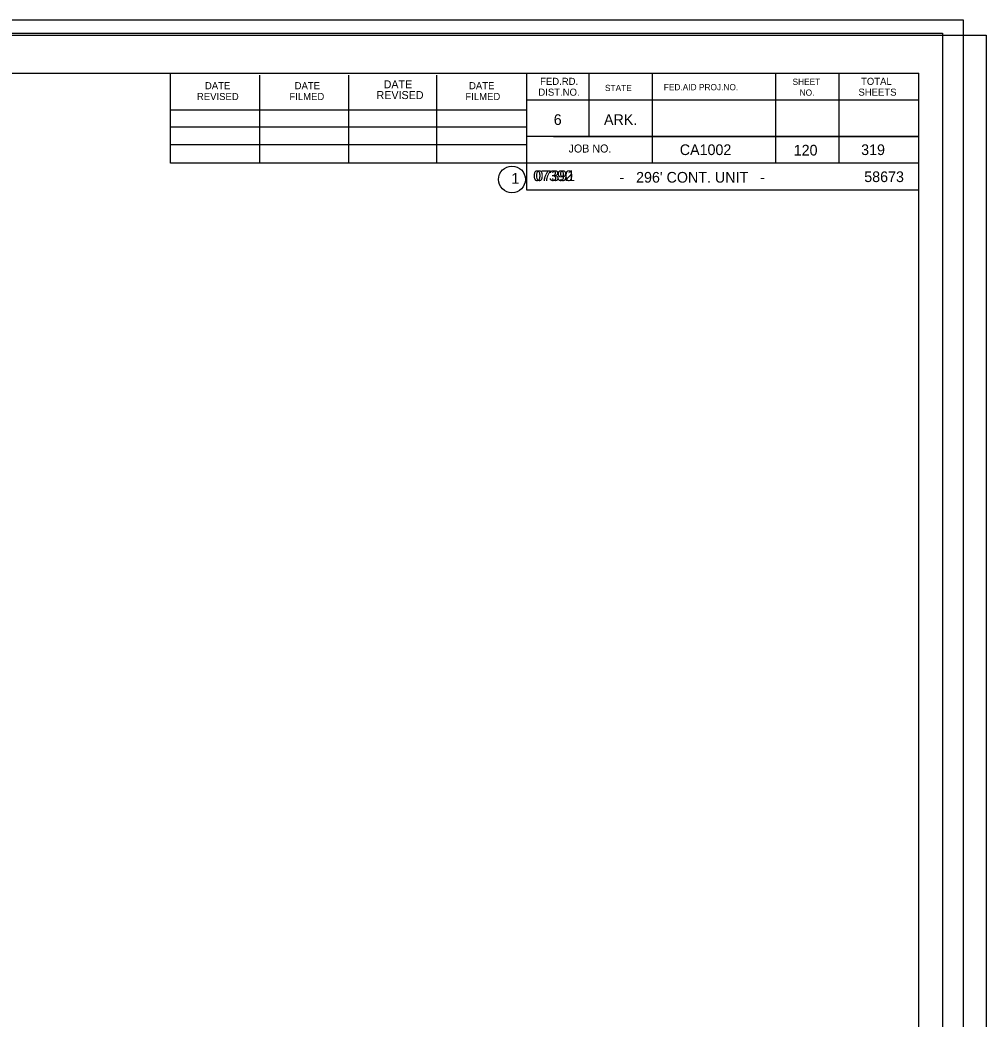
# Model space of a CAD drawing. Extents: x 208.5 to 250.5, y 328.7 to 350.7.
# Drawn here: x 232.41 to 243.03, y 339.73 to 350.71 of the extents above; entities that cross this region are included whole.
import ezdxf

# ---------------------------------------------------------------- set-up
doc = ezdxf.new("R2010")
doc.units = 0
for name, color, linetype in [('border', 7, 'Continuous'), ('Border 2660-Hwy18 - Level 62', 7, 'Continuous'), ('Border 2660-Hwy18 - Level 63', 7, 'Continuous'), ('Border 2660-Hwy18 - Text', 7, 'Continuous'), ('Bridge No BLFR', 7, 'Continuous'), ('Bridge No BLO', 7, 'Continuous'), ('Bridge No Ditch 81', 7, 'Continuous'), ('Level 62 PDF', 7, 'Continuous'), ('Text', 7, 'Continuous'), ('Title Text', 7, 'Continuous')]:
    doc.layers.add(name, color=color, linetype=linetype)

msp = doc.modelspace()

# ---------------------------------------------------------------- linework, layer by layer
at = {"layer": 'border'}
for p, q in [((210.28, 350.129), (242.291, 350.129)), ((234.065, 349.142), (234.065, 350.129)), ((235.05, 349.142), (235.05, 350.11)), ((236.027, 349.142), (236.027, 350.11)), ((236.994, 349.142), (236.994, 350.11)), ((237.98, 350.129), (237.98, 348.85)), ((238.664, 350.129), (238.664, 349.436)), ((239.359, 350.129), (239.359, 349.142)), ((240.716, 350.129), (240.716, 349.142)), ((241.411, 350.129), (241.411, 349.142)), ((242.291, 329.584), (242.291, 350.129)), ((242.291, 349.835), (237.98, 349.835)), ((242.291, 349.838), (242.291, 349.838)), ((234.065, 349.727), (237.98, 349.727)), ((234.065, 349.541), (237.98, 349.541)), ((242.291, 349.436), (237.98, 349.436)), ((238.277, 349.436), (242.291, 349.436)), ((234.065, 349.142), (234.065, 349.348)), ((234.065, 349.348), (237.98, 349.348)), ((242.291, 349.142), (234.065, 349.142)), ((237.98, 348.85), (242.291, 348.85))]:
    msp.add_line(p, q, dxfattribs=at)
msp.add_circle((237.819, 348.963), 0.147, dxfattribs=at)
at = {"layer": 'Border 2660-Hwy18 - Level 62'}
msp.add_lwpolyline([(208.659, 350.715), (242.778, 350.715), (242.778, 328.905), (208.659, 328.905)], close=True, dxfattribs=at)
at = {"layer": 'Border 2660-Hwy18 - Level 63'}
msp.add_lwpolyline([(208.548, 350.572), (242.548, 350.572), (242.548, 329.202), (208.548, 329.202)], close=True, dxfattribs=at)
at = {"layer": 'Level 62 PDF'}
msp.add_lwpolyline([(208.909, 350.548), (243.028, 350.548), (243.028, 328.739), (208.909, 328.739)], close=True, dxfattribs=at)

# ---------------------------------------------------------------- texts
at = {"layer": 'Border 2660-Hwy18 - Text'}
for s, height, p in [('FED.RD.', 0.0782, (238.128, 350.002)), ('TOTAL', 0.0782, (241.655, 350.002)), ('DATE', 0.0782, (234.445, 349.954)), ('DATE', 0.0782, (235.431, 349.954)), ('DATE', 0.0879, (236.409, 349.964)), ('DATE', 0.0782, (237.347, 349.954)), ('STATE', 0.0684, (238.841, 349.934)), ('FED.AID PROJ.NO.', 0.06839, (239.487, 349.943)), ('SHEET', 0.0684, (240.902, 350.002)), ('REVISED', 0.0782, (234.357, 349.835)), ('FILMED', 0.0782, (235.373, 349.835)), ('REVISED', 0.0879, (236.331, 349.846)), ('FILMED', 0.0782, (237.307, 349.835)), ('DIST.NO.', 0.0782, (238.109, 349.883)), ('NO.', 0.0684, (240.98, 349.883)), ('SHEETS', 0.0782, (241.626, 349.883)), ('6', 0.117, (238.278, 349.562)), ('ARK.', 0.1172, (238.83, 349.562)), ('JOB NO.', 0.0879, (238.441, 349.259)), ('CA1002', 0.1172, (239.663, 349.231)), ('319', 0.1172, (241.656, 349.231)), ('1', 0.117, (237.812, 348.916))]:
    msp.add_text(s, height=height, dxfattribs=at).set_placement(p)
at = {"layer": 'Bridge No BLFR'}
msp.add_text('07392', height=0.1172, dxfattribs=at).set_placement((238.051, 348.945))
at = {"layer": 'Bridge No BLO'}
msp.add_text('07391', height=0.1172, dxfattribs=at).set_placement((238.077, 348.945))
at = {"layer": 'Bridge No Ditch 81'}
msp.add_text('07390', height=0.1172, dxfattribs=at).set_placement((238.052, 348.945))
at = {"layer": 'Text'}
msp.add_text('120', height=0.1172, dxfattribs=at).set_placement((240.915, 349.226))
at = {"layer": 'Title Text'}
for s, height, p in [("-   296' CONT. UNIT   -", 0.11722, (239, 348.928)), ('58673', 0.1172, (241.69, 348.934))]:
    msp.add_text(s, height=height, dxfattribs=at).set_placement(p)

doc.saveas('drawing.dxf')
